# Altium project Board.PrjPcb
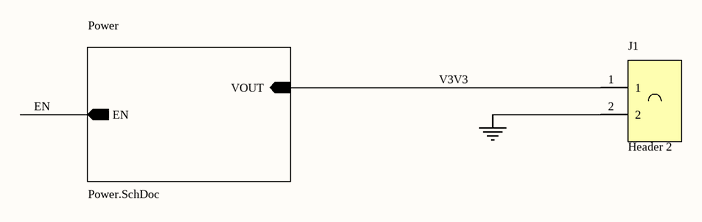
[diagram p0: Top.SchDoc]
2 sheets, 3 parts. Net scope: hierarchical (ports join the sheet entries above them; power ports are global).
Board file: Board.PcbDoc
Sheets:
  Top.SchDoc
    Power = Power.SchDoc

## Sheet Top.SchDoc: Altium test top
size A4

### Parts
J1  Header 2

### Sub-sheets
Power = Power.SchDoc: VOUT (in), EN (out)

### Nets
GND: J1.2
V3V3: J1.1 ; sheet Power/VOUT

## Sheet Power.SchDoc
size A4
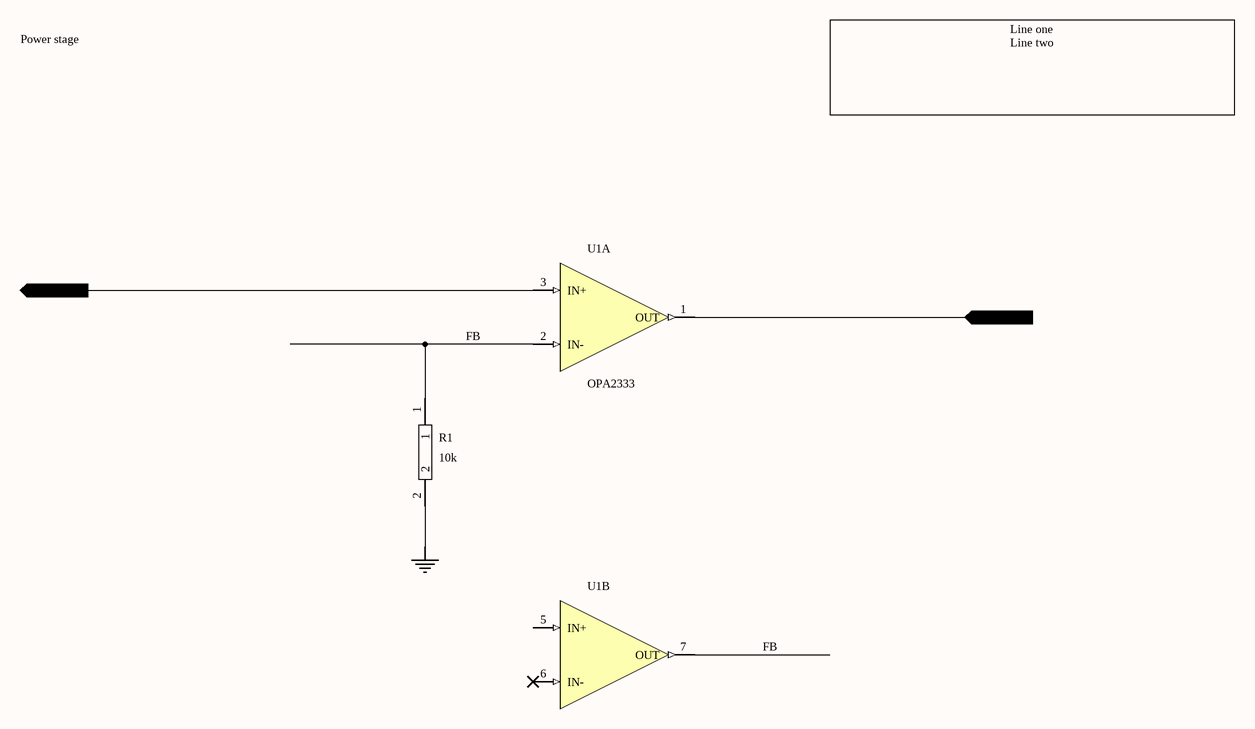
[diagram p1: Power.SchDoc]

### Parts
R1  10k
U1  OPA2333  (parts A,B of 2)

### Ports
EN (out), VOUT (in)

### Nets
GND: R1.2
EN: U1.3(IN+) ; port EN
FB: R1.1 U1.2(IN-) U1.7(OUT)
V3V3: U1.1(OUT) ; port VOUT

Not connected (* = marked no-connect by the designer): U1 5(IN+) 6(IN-)*

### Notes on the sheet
- Power stage
- Line one
  Line two

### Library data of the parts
R1 = Res

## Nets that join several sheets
GND: Top (J1.2), Power (R1.2)
V3V3: Top (J1.1), Power (U1.1)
